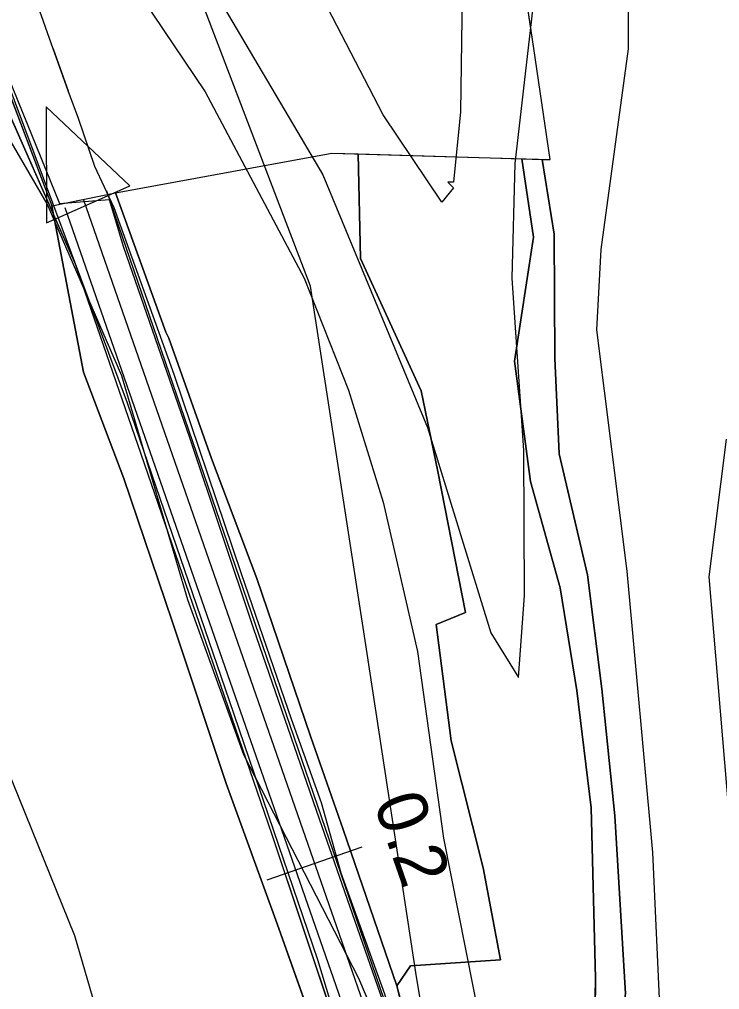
# Model space of a CAD drawing. Extents: x -662620 to -656370, y -1067090 to -1062990.
# Drawn here: x -660631.5 to -660561.8, y -1064467.9 to -1064371.3 of the extents above; entities that cross this region are included whole.
import ezdxf

# ---------------------------------------------------------------- set-up
doc = ezdxf.new("R2010")
doc.units = 0
for name, color, linetype in [('CESTA_ZABOR', 7, 'Continuous'), ('Default', 7, 'Continuous'), ('ELEK__VEDENÍ_VN_-_NADZEMNÍ', 7, 'Continuous'), ('OBVOD_PÚ', 7, 'Continuous'), ('Odvodnení_cesty_príkopem_-_navržené', 7, 'Continuous'), ('ORNÁ_PŮDA_-_STÁVAJÍCÍ', 7, 'Continuous'), ('OSTATNÍ_PLOCHA_-_STÁVAJÍCÍ', 7, 'Continuous'), ('POLNÍ_CESTA_NAVRŽENÁ_-_OSA', 7, 'Continuous'), ('POLNÍ_CESTA_STÁVAJÍCÍ_-_KRAJ', 7, 'Continuous'), ('Popis_objektú_polních_cest_stávajících', 7, 'Continuous'), ('SDELOVACÍ_VEDENÍ_-_PODZEMNÍ', 7, 'Continuous'), ('VODNÍ_PLOCHA_-_STÁVAJÍCÍ', 7, 'Continuous'), ('VRSTEVNICE_ZDŮRAZNĚNÁ', 7, 'Continuous'), ('VRSTEVNICE_ZÁKLADNÍ', 7, 'Continuous')]:
    doc.layers.add(name, color=color, linetype=linetype)

msp = doc.modelspace()

# ---------------------------------------------------------------- linework, layer by layer
at = {"layer": 'CESTA_ZABOR'}
for p, q in [((-660625.928, -1064395.696), (-660633.877, -1064377.704)), ((-660632.6, -1064377.131), (-660627.53, -1064389.656)), ((-660627.53, -1064389.656), (-660622.577, -1064389.254)), ((-660622.577, -1064389.254), (-660621.175, -1064393.993)), ((-660621.175, -1064393.993), (-660614.584, -1064412.937)), ((-660619.417, -1064414.6), (-660625.928, -1064395.696)), ((-660614.584, -1064412.937), (-660608.241, -1064431.905)), ((-660612.904, -1064433.509), (-660619.417, -1064414.6)), ((-660608.241, -1064431.905), (-660601.661, -1064450.917)), ((-660606.392, -1064452.417), (-660612.904, -1064433.509)), ((-660601.661, -1064450.917), (-660595.091, -1064469.801)), ((-660600.062, -1064471.367), (-660606.392, -1064452.417))]:
    msp.add_line(p, q, dxfattribs=at)
for points in [[(-660561.221, -1064530.082), (-660567.039, -1064529.645), (-660572.895, -1064528.072), (-660576.636, -1064526.5), (-660583.42, -1064522.342), (-660588.16, -1064517.199), (-660590.8, -1064512.663), (-660591.322, -1064510.407), (-660593.362, -1064504.735), (-660594.424, -1064496.171), (-660595.374, -1064490.272), (-660600.062, -1064471.367), (-660606.392, -1064452.417), (-660612.904, -1064433.509), (-660619.417, -1064414.6), (-660625.928, -1064395.696), (-660633.877, -1064377.704), (-660641.399, -1064359.045)], [(-660638.814, -1064359.785), (-660632.6, -1064377.131), (-660627.53, -1064389.656), (-660622.577, -1064389.254), (-660621.175, -1064393.993), (-660614.584, -1064412.937), (-660608.241, -1064431.905), (-660601.661, -1064450.917), (-660595.091, -1064469.801), (-660591.584, -1064479.727), (-660590.282, -1064484.966), (-660589.785, -1064489.309), (-660588.169, -1064498.645), (-660587.48, -1064503.432), (-660585.955, -1064508.272), (-660583.722, -1064512.181), (-660580.549, -1064516.324), (-660573.921, -1064521.239), (-660569.623, -1064522.832), (-660562.733, -1064523.742), (-660556.454, -1064523.208)]]:
    msp.add_lwpolyline(points, dxfattribs=at)
at = {"layer": 'ELEK__VEDENÍ_VN_-_NADZEMNÍ'}
msp.add_lwpolyline([(-660486.16, -1064672.33), (-660496.43, -1064657.61), (-660505.74, -1064639.3), (-660516.2, -1064611.04), (-660527.14, -1064585.11), (-660549.29, -1064531.06), (-660585.83, -1064502.91), (-660591.97, -1064466.66), (-660596.98, -1064434.04), (-660602.53, -1064397.87), (-660615.27, -1064364.48)], dxfattribs=at)
at = {"layer": 'OBVOD_PÚ'}
for points in [[(-660580.3, -1064374.21), (-660584.19, -1064348.03)], [(-660635.14, -1064371.85), (-660628.31, -1064389.87)], [(-660578.66, -1064385.28), (-660580.3, -1064374.21)], [(-660621.95, -1064388.59), (-660600.43, -1064384.62)], [(-660600.43, -1064384.62), (-660584.66, -1064385.1)], [(-660584.66, -1064385.1), (-660578.66, -1064385.28)], [(-660628.31, -1064389.87), (-660621.95, -1064388.59)]]:
    msp.add_lwpolyline(points, dxfattribs=at)
at = {"layer": 'Odvodnení_cesty_príkopem_-_navržené'}
msp.add_lwpolyline([(-660639.399, -1064359.671), (-660620.796, -1064409.489), (-660610.639, -1064439.162), (-660601.851, -1064464.955), (-660599.682, -1064472.088), (-660596.03, -1064486.526), (-660594.718, -1064492.346), (-660593.177, -1064504.615), (-660590.78, -1064511.577), (-660590.381, -1064513.175), (-660587.87, -1064517.112), (-660582.962, -1064522.533), (-660575.658, -1064526.699), (-660567.726, -1064529.21), (-660560.993, -1064529.837), (-660553.574, -1064528.354), (-660545.927, -1064524.759), (-660535.941, -1064517.569), (-660510.034, -1064499.993), (-660496.281, -1064490.92), (-660489.833, -1064487.781), (-660480.703, -1064485.099), (-660471.173, -1064485.841), (-660468.605, -1064488.865)], dxfattribs=at)
at = {"layer": 'ORNÁ_PŮDA_-_STÁVAJÍCÍ'}
for p, q in [((-660635.14, -1064371.85), (-660628.31, -1064389.87)), ((-660621.95, -1064388.59), (-660600.43, -1064384.62)), ((-660600.43, -1064384.62), (-660597.802, -1064384.7)), ((-660597.802, -1064384.7), (-660597.57, -1064395.11)), ((-660616.93, -1064402.47), (-660621.95, -1064388.59)), ((-660628.31, -1064389.87), (-660625.13, -1064406.44)), ((-660597.57, -1064395.11), (-660591.53, -1064408.3)), ((-660616.63, -1064403.06), (-660616.93, -1064402.47)), ((-660612.4, -1064415.03), (-660616.63, -1064403.06)), ((-660625.13, -1064406.44), (-660621.13, -1064417.02)), ((-660591.53, -1064408.3), (-660589.86, -1064416.33)), ((-660607.87, -1064427), (-660612.4, -1064415.03)), ((-660589.86, -1064416.33), (-660587.11, -1064430.37)), ((-660621.13, -1064417.02), (-660616.3, -1064431.25)), ((-660602.54, -1064442.7), (-660607.87, -1064427)), ((-660587.11, -1064430.37), (-660590.03, -1064431.59)), ((-660616.3, -1064431.25), (-660610.95, -1064447.41)), ((-660590.03, -1064431.59), (-660588.55, -1064443.15)), ((-660599.3, -1064452.01), (-660602.54, -1064442.7)), ((-660588.55, -1064443.15), (-660585.35, -1064455.81)), ((-660610.95, -1064447.41), (-660605.85, -1064461.4)), ((-660593.94, -1064467.56), (-660599.3, -1064452.01)), ((-660585.35, -1064455.81), (-660583.62, -1064464.99)), ((-660605.85, -1064461.4), (-660601.67, -1064473.19)), ((-660592.58, -1064465.56), (-660593.94, -1064467.56)), ((-660583.62, -1064464.99), (-660592.58, -1064465.56))]:
    msp.add_line(p, q, dxfattribs=at)
msp.add_lwpolyline([(-660644.04, -1064349.49), (-660635.14, -1064371.85), (-660628.31, -1064389.87), (-660625.13, -1064406.44), (-660621.13, -1064417.02), (-660616.3, -1064431.25), (-660610.95, -1064447.41), (-660605.85, -1064461.4), (-660601.67, -1064473.19), (-660599.52, -1064481.13), (-660598.31, -1064492.19), (-660599.59, -1064501.78), (-660602.49, -1064513.19), (-660606.48, -1064523.57), (-660611.91, -1064534.23), (-660617.63, -1064543.32)], dxfattribs=at)
msp.add_lwpolyline([(-660597.802, -1064384.7), (-660597.57, -1064395.11), (-660591.53, -1064408.3), (-660589.86, -1064416.33), (-660587.11, -1064430.37), (-660590.03, -1064431.59), (-660588.55, -1064443.15), (-660585.35, -1064455.81), (-660583.62, -1064464.99), (-660592.58, -1064465.56), (-660593.94, -1064467.56), (-660599.3, -1064452.01), (-660602.54, -1064442.7), (-660607.87, -1064427), (-660612.4, -1064415.03), (-660616.63, -1064403.06), (-660616.93, -1064402.47), (-660621.95, -1064388.59), (-660600.43, -1064384.62)], close=True, dxfattribs=at)
at = {"layer": 'OSTATNÍ_PLOCHA_-_STÁVAJÍCÍ'}
for p, q in [((-660580.3, -1064374.21), (-660584.19, -1064348.03)), ((-660580.3, -1064374.21), (-660584.19, -1064348.03)), ((-660578.66, -1064385.28), (-660580.3, -1064374.21)), ((-660578.66, -1064385.28), (-660580.3, -1064374.21)), ((-660597.57, -1064395.11), (-660597.802, -1064384.7)), ((-660597.802, -1064384.7), (-660584.66, -1064385.1)), ((-660597.57, -1064395.11), (-660597.802, -1064384.7)), ((-660597.802, -1064384.7), (-660584.66, -1064385.1)), ((-660584.66, -1064385.1), (-660581.507, -1064385.195)), ((-660584.66, -1064385.1), (-660581.507, -1064385.195)), ((-660581.507, -1064385.195), (-660580.32, -1064392.99)), ((-660581.507, -1064385.195), (-660580.32, -1064392.99)), ((-660578.27, -1064392.71), (-660579.458, -1064385.256)), ((-660579.458, -1064385.256), (-660578.66, -1064385.28)), ((-660578.27, -1064392.71), (-660579.458, -1064385.256)), ((-660579.458, -1064385.256), (-660578.66, -1064385.28)), ((-660628.31, -1064389.87), (-660621.95, -1064388.59)), ((-660628.31, -1064389.87), (-660621.95, -1064388.59)), ((-660621.95, -1064388.59), (-660616.93, -1064402.47)), ((-660621.95, -1064388.59), (-660616.93, -1064402.47)), ((-660625.13, -1064406.44), (-660628.31, -1064389.87)), ((-660625.13, -1064406.44), (-660628.31, -1064389.87)), ((-660580.32, -1064392.99), (-660582.24, -1064405.35)), ((-660580.32, -1064392.99), (-660582.24, -1064405.35)), ((-660578.22, -1064405.06), (-660578.27, -1064392.71)), ((-660578.22, -1064405.06), (-660578.27, -1064392.71)), ((-660591.53, -1064408.3), (-660597.57, -1064395.11)), ((-660591.53, -1064408.3), (-660597.57, -1064395.11)), ((-660616.93, -1064402.47), (-660616.63, -1064403.06)), ((-660616.93, -1064402.47), (-660616.63, -1064403.06)), ((-660616.63, -1064403.06), (-660612.4, -1064415.03)), ((-660616.63, -1064403.06), (-660612.4, -1064415.03)), ((-660582.24, -1064405.35), (-660580.64, -1064417.35)), ((-660582.24, -1064405.35), (-660580.64, -1064417.35)), ((-660577.78, -1064414.57), (-660578.22, -1064405.06)), ((-660577.78, -1064414.57), (-660578.22, -1064405.06)), ((-660621.13, -1064417.02), (-660625.13, -1064406.44)), ((-660621.13, -1064417.02), (-660625.13, -1064406.44)), ((-660589.86, -1064416.33), (-660591.53, -1064408.3)), ((-660589.86, -1064416.33), (-660591.53, -1064408.3)), ((-660612.4, -1064415.03), (-660607.87, -1064427)), ((-660612.4, -1064415.03), (-660607.87, -1064427)), ((-660574.96, -1064426.63), (-660577.78, -1064414.57)), ((-660574.96, -1064426.63), (-660577.78, -1064414.57)), ((-660587.11, -1064430.37), (-660589.86, -1064416.33)), ((-660587.11, -1064430.37), (-660589.86, -1064416.33)), ((-660616.3, -1064431.25), (-660621.13, -1064417.02)), ((-660616.3, -1064431.25), (-660621.13, -1064417.02)), ((-660580.64, -1064417.35), (-660577.67, -1064427.92)), ((-660580.64, -1064417.35), (-660577.67, -1064427.92)), ((-660607.87, -1064427), (-660602.54, -1064442.7)), ((-660607.87, -1064427), (-660602.54, -1064442.7)), ((-660573.53, -1064437.99), (-660574.96, -1064426.63)), ((-660573.53, -1064437.99), (-660574.96, -1064426.63)), ((-660577.67, -1064427.92), (-660576.01, -1064438.15)), ((-660577.67, -1064427.92), (-660576.01, -1064438.15)), ((-660590.03, -1064431.59), (-660587.11, -1064430.37)), ((-660590.03, -1064431.59), (-660587.11, -1064430.37)), ((-660610.95, -1064447.41), (-660616.3, -1064431.25)), ((-660610.95, -1064447.41), (-660616.3, -1064431.25)), ((-660588.55, -1064443.15), (-660590.03, -1064431.59)), ((-660588.55, -1064443.15), (-660590.03, -1064431.59)), ((-660576.01, -1064438.15), (-660574.6, -1064449.85)), ((-660576.01, -1064438.15), (-660574.6, -1064449.85)), ((-660572.23, -1064450.62), (-660573.53, -1064437.99)), ((-660572.23, -1064450.62), (-660573.53, -1064437.99)), ((-660602.54, -1064442.7), (-660599.3, -1064452.01)), ((-660602.54, -1064442.7), (-660599.3, -1064452.01)), ((-660585.35, -1064455.81), (-660588.55, -1064443.15)), ((-660585.35, -1064455.81), (-660588.55, -1064443.15)), ((-660605.85, -1064461.4), (-660610.95, -1064447.41)), ((-660605.85, -1064461.4), (-660610.95, -1064447.41)), ((-660574.6, -1064449.85), (-660574.15, -1064466.8)), ((-660574.6, -1064449.85), (-660574.15, -1064466.8)), ((-660571.16, -1064468.32), (-660572.23, -1064450.62)), ((-660571.16, -1064468.32), (-660572.23, -1064450.62)), ((-660599.3, -1064452.01), (-660593.94, -1064467.56)), ((-660599.3, -1064452.01), (-660593.94, -1064467.56)), ((-660583.62, -1064464.99), (-660585.35, -1064455.81)), ((-660583.62, -1064464.99), (-660585.35, -1064455.81)), ((-660601.67, -1064473.19), (-660605.85, -1064461.4)), ((-660601.67, -1064473.19), (-660605.85, -1064461.4)), ((-660593.94, -1064467.56), (-660592.58, -1064465.56)), ((-660593.94, -1064467.56), (-660592.58, -1064465.56)), ((-660592.58, -1064465.56), (-660583.62, -1064464.99)), ((-660592.58, -1064465.56), (-660583.62, -1064464.99)), ((-660589.52, -1064484.4), (-660593.94, -1064467.56)), ((-660593.94, -1064467.56), (-660589.52, -1064484.4)), ((-660589.52, -1064484.4), (-660593.94, -1064467.56)), ((-660593.94, -1064467.56), (-660589.52, -1064484.4)), ((-660574.15, -1064466.8), (-660574.32, -1064476.38)), ((-660574.15, -1064466.8), (-660574.32, -1064476.38))]:
    msp.add_line(p, q, dxfattribs=at)
for points in [[(-660562.39, -1064537.71), (-660564.53, -1064533.41), (-660569.11, -1064530.3), (-660575.91, -1064528.09), (-660583.41, -1064525.01), (-660575.14, -1064508.54), (-660568.31, -1064498.51), (-660569.74, -1064486.95), (-660572.39, -1064476.63), (-660571.16, -1064468.32), (-660572.23, -1064450.62), (-660573.53, -1064437.99), (-660574.96, -1064426.63), (-660577.78, -1064414.57), (-660578.22, -1064405.06), (-660578.27, -1064392.71), (-660579.458, -1064385.256), (-660578.66, -1064385.28), (-660580.3, -1064374.21), (-660584.19, -1064348.03)], [(-660562.39, -1064537.71), (-660564.53, -1064533.41), (-660569.11, -1064530.3), (-660575.91, -1064528.09), (-660583.41, -1064525.01), (-660575.14, -1064508.54), (-660568.31, -1064498.51), (-660569.74, -1064486.95), (-660572.39, -1064476.63), (-660571.16, -1064468.32), (-660572.23, -1064450.62), (-660573.53, -1064437.99), (-660574.96, -1064426.63), (-660577.78, -1064414.57), (-660578.22, -1064405.06), (-660578.27, -1064392.71), (-660579.458, -1064385.256), (-660578.66, -1064385.28), (-660580.3, -1064374.21), (-660584.19, -1064348.03)], [(-660589.52, -1064484.4), (-660593.94, -1064467.56), (-660592.58, -1064465.56), (-660583.62, -1064464.99), (-660585.35, -1064455.81), (-660588.55, -1064443.15), (-660590.03, -1064431.59), (-660587.11, -1064430.37), (-660589.86, -1064416.33), (-660591.53, -1064408.3), (-660597.57, -1064395.11), (-660597.802, -1064384.7), (-660584.66, -1064385.1), (-660581.507, -1064385.195), (-660580.32, -1064392.99), (-660582.24, -1064405.35), (-660580.64, -1064417.35), (-660577.67, -1064427.92), (-660576.01, -1064438.15), (-660574.6, -1064449.85), (-660574.15, -1064466.8), (-660574.32, -1064476.38)], [(-660589.52, -1064484.4), (-660593.94, -1064467.56), (-660592.58, -1064465.56), (-660583.62, -1064464.99), (-660585.35, -1064455.81), (-660588.55, -1064443.15), (-660590.03, -1064431.59), (-660587.11, -1064430.37), (-660589.86, -1064416.33), (-660591.53, -1064408.3), (-660597.57, -1064395.11), (-660597.802, -1064384.7), (-660584.66, -1064385.1), (-660581.507, -1064385.195), (-660580.32, -1064392.99), (-660582.24, -1064405.35), (-660580.64, -1064417.35), (-660577.67, -1064427.92), (-660576.01, -1064438.15), (-660574.6, -1064449.85), (-660574.15, -1064466.8), (-660574.32, -1064476.38)], [(-660601.67, -1064473.19), (-660605.85, -1064461.4), (-660610.95, -1064447.41), (-660616.3, -1064431.25), (-660621.13, -1064417.02), (-660625.13, -1064406.44), (-660628.31, -1064389.87), (-660621.95, -1064388.59), (-660616.93, -1064402.47), (-660616.63, -1064403.06), (-660612.4, -1064415.03), (-660607.87, -1064427), (-660602.54, -1064442.7), (-660599.3, -1064452.01), (-660593.94, -1064467.56), (-660589.52, -1064484.4)], [(-660601.67, -1064473.19), (-660605.85, -1064461.4), (-660610.95, -1064447.41), (-660616.3, -1064431.25), (-660621.13, -1064417.02), (-660625.13, -1064406.44), (-660628.31, -1064389.87), (-660621.95, -1064388.59), (-660616.93, -1064402.47), (-660616.63, -1064403.06), (-660612.4, -1064415.03), (-660607.87, -1064427), (-660602.54, -1064442.7), (-660599.3, -1064452.01), (-660593.94, -1064467.56), (-660589.52, -1064484.4)]]:
    msp.add_lwpolyline(points, dxfattribs=at)
at = {"layer": 'POLNÍ_CESTA_NAVRŽENÁ_-_OSA'}
for points in [[(-660465.581, -1064481), (-660485.651, -1064483.365), (-660500.623, -1064490.842), (-660531.756, -1064512.013), (-660548.765, -1064524.994), (-660562.869, -1064527.215), (-660575.809, -1064524.823), (-660586.118, -1064515.966), (-660590.055, -1064503.029), (-660592.117, -1064484.093), (-660625.123, -1064389.329)], [(-660606.842, -1064457.018), (-660597.398, -1064453.729)]]:
    msp.add_lwpolyline(points, dxfattribs=at)
at = {"layer": 'POLNÍ_CESTA_STÁVAJÍCÍ_-_KRAJ'}
for points in [[(-660465.815, -1064479.013), (-660486.232, -1064481.42), (-660501.637, -1064489.113), (-660532.926, -1064510.39), (-660549.576, -1064523.097), (-660562.842, -1064525.186), (-660574.915, -1064522.954), (-660584.374, -1064514.827), (-660588.087, -1064502.626), (-660590.154, -1064483.65), (-660622.805, -1064388.403)], [(-660465.347, -1064482.986), (-660485.07, -1064485.311), (-660499.609, -1064492.572), (-660530.586, -1064513.636), (-660547.954, -1064526.891), (-660562.896, -1064529.244), (-660576.703, -1064526.692), (-660587.862, -1064517.104), (-660592.023, -1064503.432), (-660594.081, -1064484.535), (-660626.961, -1064390.065)]]:
    msp.add_lwpolyline(points, dxfattribs=at)
at = {"layer": 'Popis_objektú_polních_cest_stávajících'}
for p, q in [((-660620.528, -1064387.874), (-660628.862, -1064380.004)), ((-660628.862, -1064380.004), (-660628.819, -1064391.569)), ((-660624.555, -1064389.669), (-660620.528, -1064387.874)), ((-660628.819, -1064391.569), (-660624.555, -1064389.669))]:
    msp.add_line(p, q, dxfattribs=at)
msp.add_lwpolyline([(-660620.528, -1064387.874), (-660628.862, -1064380.004), (-660628.819, -1064391.569), (-660624.555, -1064389.669)], close=True, dxfattribs=at)
at = {"layer": 'SDELOVACÍ_VEDENÍ_-_PODZEMNÍ'}
for points in [[(-660557.17, -1064524.32), (-660563.7, -1064524.75), (-660570.89, -1064523.5), (-660578.3, -1064519.9), (-660582.83, -1064515.76), (-660585.76, -1064510.93), (-660587.47, -1064505.76), (-660587.89, -1064503.71), (-660588.65, -1064497.83), (-660589.21, -1064490.19), (-660591.5, -1064480.57), (-660595.13, -1064468.41), (-660599.47, -1064456.33), (-660601.44, -1064449.33), (-660604.44, -1064440.99), (-660609.4, -1064426.52), (-660616.1, -1064406.68), (-660622.09, -1064390.09), (-660624.03, -1064385.97), (-660625.63, -1064381.19), (-660626.67, -1064378.41), (-660628.17, -1064374.23), (-660630.45, -1064367.74)], [(-660557.17, -1064524.32), (-660563.7, -1064524.75), (-660570.89, -1064523.5), (-660578.3, -1064519.9), (-660582.83, -1064515.76), (-660585.76, -1064510.93), (-660587.47, -1064505.76), (-660587.89, -1064503.71), (-660588.65, -1064497.83), (-660589.21, -1064490.19), (-660591.5, -1064480.57), (-660595.13, -1064468.41), (-660599.47, -1064456.33), (-660601.44, -1064449.33), (-660604.44, -1064440.99), (-660609.4, -1064426.52), (-660616.1, -1064406.68), (-660622.09, -1064390.09), (-660624.03, -1064385.97), (-660625.63, -1064381.19), (-660626.67, -1064378.41), (-660628.17, -1064374.23), (-660630.45, -1064367.74)], [(-660628.17, -1064374.23), (-660626.67, -1064378.41)], [(-660628.17, -1064374.23), (-660626.67, -1064378.41)]]:
    msp.add_lwpolyline(points, dxfattribs=at)
at = {"layer": 'VODNÍ_PLOCHA_-_STÁVAJÍCÍ'}
for p, q in [((-660580.32, -1064392.99), (-660581.507, -1064385.195)), ((-660581.507, -1064385.195), (-660579.458, -1064385.256)), ((-660579.458, -1064385.256), (-660578.27, -1064392.71)), ((-660582.24, -1064405.35), (-660580.32, -1064392.99)), ((-660578.27, -1064392.71), (-660578.22, -1064405.06)), ((-660580.64, -1064417.35), (-660582.24, -1064405.35)), ((-660578.22, -1064405.06), (-660577.78, -1064414.57)), ((-660577.78, -1064414.57), (-660574.96, -1064426.63)), ((-660577.67, -1064427.92), (-660580.64, -1064417.35)), ((-660574.96, -1064426.63), (-660573.53, -1064437.99)), ((-660576.01, -1064438.15), (-660577.67, -1064427.92)), ((-660574.6, -1064449.85), (-660576.01, -1064438.15)), ((-660573.53, -1064437.99), (-660572.23, -1064450.62)), ((-660574.15, -1064466.8), (-660574.6, -1064449.85)), ((-660572.23, -1064450.62), (-660571.16, -1064468.32)), ((-660574.32, -1064476.38), (-660574.15, -1064466.8))]:
    msp.add_line(p, q, dxfattribs=at)
msp.add_lwpolyline([(-660579.458, -1064385.256), (-660578.27, -1064392.71), (-660578.22, -1064405.06), (-660577.78, -1064414.57), (-660574.96, -1064426.63), (-660573.53, -1064437.99), (-660572.23, -1064450.62), (-660571.16, -1064468.32), (-660572.39, -1064476.63), (-660569.74, -1064486.95), (-660568.31, -1064498.51), (-660575.14, -1064508.54), (-660576.59, -1064507.39), (-660571.43, -1064498.18), (-660571.7, -1064486.51), (-660574.32, -1064476.38), (-660574.15, -1064466.8), (-660574.6, -1064449.85), (-660576.01, -1064438.15), (-660577.67, -1064427.92), (-660580.64, -1064417.35), (-660582.24, -1064405.35), (-660580.32, -1064392.99), (-660581.507, -1064385.195)], close=True, dxfattribs=at)
at = {"layer": 'VRSTEVNICE_ZDŮRAZNĚNÁ'}
msp.add_lwpolyline([(-660629.761, -1064353.646), (-660613.038, -1064378.517), (-660603.176, -1064397.099), (-660598.745, -1064408.247), (-660595.314, -1064419.396), (-660591.884, -1064434.261), (-660589.311, -1064452.842), (-660584.88, -1064475.14), (-660583.022, -1064493.721), (-660581.45, -1064497.437), (-660577.305, -1064501.868), (-660574.303, -1064502.011), (-660568.586, -1064498.009), (-660566.013, -1064490.291), (-660565.87, -1064486.289), (-660567.728, -1064470.28), (-660568.443, -1064454.272), (-660571.016, -1064426.257), (-660574.017, -1064402.244), (-660573.588, -1064394.24), (-660570.873, -1064374.229), (-660570.873, -1064346.214)], dxfattribs=at)
at = {"layer": 'VRSTEVNICE_ZÁKLADNÍ'}
for points in [[(-660616.325, -1064361.365), (-660601.317, -1064386.807), (-660590.883, -1064411.964), (-660584.595, -1064432.403), (-660581.822, -1064436.863), (-660581.227, -1064428.687), (-660581.307, -1064414.25), (-660582.45, -1064397.099), (-660582.164, -1064385.664), (-660574.589, -1064319.915)], [(-660616.325, -1064361.365), (-660601.317, -1064386.807), (-660590.883, -1064411.964), (-660584.595, -1064432.403), (-660581.822, -1064436.863), (-660581.227, -1064428.687), (-660581.307, -1064414.25), (-660582.45, -1064397.099), (-660582.164, -1064385.664), (-660574.589, -1064319.915)], [(-660587.167, -1064350.217), (-660587.596, -1064380.518), (-660588.311, -1064387.522), (-660588.882, -1064387.522), (-660588.311, -1064388.093), (-660589.454, -1064389.523), (-660595.314, -1064380.804), (-660603.604, -1064364.796)], [(-660587.167, -1064350.217), (-660587.596, -1064380.518), (-660588.311, -1064387.522), (-660588.882, -1064387.522), (-660588.311, -1064388.093), (-660589.454, -1064389.523), (-660595.314, -1064380.804), (-660603.604, -1064364.796)], [(-660561.153, -1064509.158), (-660564.155, -1064516.019), (-660569.729, -1064524.595), (-660575.733, -1064529.311), (-660578.591, -1064529.454), (-660582.021, -1064528.739), (-660588.597, -1064523.737), (-660591.455, -1064518.306), (-660592.885, -1064511.445), (-660590.74, -1064485.717), (-660591.169, -1064482.286), (-660597.744, -1064466.85), (-660609.179, -1064444.552), (-660614.753, -1064429.115), (-660621.328, -1064406.818), (-660628.761, -1064389.666), (-660634.764, -1064379.375), (-660638.48, -1064374.229), (-660646.342, -1064365.51)], [(-660561.153, -1064509.158), (-660564.155, -1064516.019), (-660569.729, -1064524.595), (-660575.733, -1064529.311), (-660578.591, -1064529.454), (-660582.021, -1064528.739), (-660588.597, -1064523.737), (-660591.455, -1064518.306), (-660592.885, -1064511.445), (-660590.74, -1064485.717), (-660591.169, -1064482.286), (-660597.744, -1064466.85), (-660609.179, -1064444.552), (-660614.753, -1064429.115), (-660621.328, -1064406.818), (-660628.761, -1064389.666), (-660634.764, -1064379.375), (-660638.48, -1064374.229), (-660646.342, -1064365.51)], [(-660676.643, -1064391.095), (-660670.068, -1064392.524), (-660664.351, -1064395.097), (-660657.49, -1064400.243), (-660654.06, -1064403.673), (-660649.772, -1064409.391), (-660635.907, -1064438.263), (-660626.045, -1064462.562), (-660621.471, -1064478.284), (-660619.613, -1064489.719), (-660619.184, -1064496.866), (-660620.042, -1064533.885)], [(-660676.643, -1064391.095), (-660670.068, -1064392.524), (-660664.351, -1064395.097), (-660657.49, -1064400.243), (-660654.06, -1064403.673), (-660649.772, -1064409.391), (-660635.907, -1064438.263), (-660626.045, -1064462.562), (-660621.471, -1064478.284), (-660619.613, -1064489.719), (-660619.184, -1064496.866), (-660620.042, -1064533.885)], [(-660561.153, -1064413.107), (-660562.869, -1064426.829), (-660560.868, -1064450.841)], [(-660561.153, -1064413.107), (-660562.869, -1064426.829), (-660560.868, -1064450.841)]]:
    msp.add_lwpolyline(points, dxfattribs=at)

# ---------------------------------------------------------------- texts
at = {"layer": 'Default'}
msp.add_text('0.2', height=5, rotation=289.20265, dxfattribs=at).set_placement((-660596.297, -1064449.29))

doc.saveas('drawing.dxf')
